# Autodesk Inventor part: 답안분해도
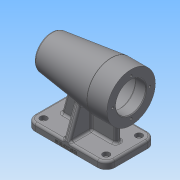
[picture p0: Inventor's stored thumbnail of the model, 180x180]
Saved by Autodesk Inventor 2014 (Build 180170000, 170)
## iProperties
Created: 2018-09
Part Number: 답안분해도
Material: 일반
Document SubType Name: Modeling
Designer: net
Density: 1 g/cm^3
Appearance: 기본값
Author: net
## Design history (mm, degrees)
sketch "스케치1"
  geometry: L1 (56, -34)-(-56, -34); L2 (-56, -34)-(-56, 34); L3 (-56, 34)-(56, 34); L4 (56, 34)-(56, -34); L5 (56, -34)-(-56, 34); L6 (-56, -34)-(56, 34); L7 (-28, 34)-(56, 23.686); L8 (50, 10.5)-(50, 0); L9 (50, 10.5)-(47, 10.5); L10 (47, 10.5)-(47, 0); L11 (47, 10.5)-(47, 16); L12 (47, 16)-(43, 16); L13 (43, 16)-(43, 0); L14 (43, 16)-(43, 17.5); L15 (43, 17.5)-(25, 17.5); L16 (25, 17.5)-(25, 0); L17 (25, 17.5)-(25, 21); L18 (25, 21)-(13, 21); L19 (13, 21)-(13, 0); L20 (13, 21)-(13, 24); L21 (13, 24)-(-41, 24); L22 (-41, 24)-(-41, 0); L23 (-41, 21)-(-56, 21); A1 r 80 centre (-20.413, 0) between (56, -23.686) and (56, 23.686); 4 further points
  constraints: 46 end point, 8 perpendicular, 5 point on line, 5 vertical, 4 collinear, 3 midpoint, 3 point on circle, 2 parallel, 1 centre point, 1 horizontal, 1 horizontal alignment, 10 other
  dimensions: "d0" = 112 distance of L2.end L3.end; "d1" = 28 distance from line of L2 L7.start; "d2" = 7 deg angle of L3 L7; "d3" = 68 dimension on L3; "d4" = 80 radius of A1; "d5" = 15 distance of L23.start L23.end; "d6" = 54 distance of L20.end L21.end; "d7" = 12 distance of L17.end L18.end; "d8" = 18 distance of L14.end L15.end; "d9" = 4 distance of L11.end L12.end; "d10" = 3 distance of L8.start L9.end; "d11" = 21 dimension on L9; "d12" = 32 dimension on L12; "d13" = 35 dimension on L15; "d14" = 42 dimension on L18; "d15" = 48 dimension on L21; "d16" = 42 dimension on L23
revolve "회전1" sketch "스케치1" stored, may be unused: angle "d17" = 90 deg
fillet "모깎기1" dims "d18" = 3
node "작업 평면1"
sketch "스케치2"
  geometry: L1 (-44, -35)-(44, -35); L2 (56, -23)-(56, 23); L3 (44, 35)-(-44, 35); L4 (-56, 23)-(-56, -23); L5 (-56, -35)-(56, 35); L6 (56, -35)-(-56, 35); A1 r 12 centre (-44, 23) between (-44, 35) and (-56, 23); A2 r 12 centre (-44, -23) between (-56, -23) and (-44, -35); A3 r 12 centre (44, -23) between (44, -35) and (56, -23); A4 r 12 centre (44, 23) between (56, 23) and (44, 35); 1 further point
  constraints: 12 end point, 8 point on circle, 8 point on line, 8 tangent, 4 centre point, 3 equal radius, 2 midpoint, 2 parallel, 1 horizontal, 1 perpendicular
  dimensions: "d20" = 112 distance of L5.end L6.end; "d21" = 70 distance of L6.start L5.end; "d22" = 12 radius of A1
extrude "돌출1" join sketch "스케치2" distance "d23" = 10; taper "d24" = 0 deg
sketch "스케치5"
  geometry: L1 (56, -23)-(56, 23) reference; L2 (-38, -4)-(38, -4); L3 (38, -4)-(38, 4); L4 (38, 4)-(-38, 4); L5 (-38, 4)-(-38, -4); L6 (-38, -4)-(38, 4); L7 (38, -4)-(-38, 4); 1 further point
  constraints: 12 end point, 2 midpoint, 2 parallel, 1 horizontal, 1 perpendicular
  dimensions: "d32" = 8 distance of L2.end L3.end; "d33" = 18 distance between parallel lines of L1 L3
extrude "돌출3" join sketch "스케치5" stored distance "d34" = 8; taper "d35" = 0 deg
feature "면 기울기1" dims angle "d36" = 15 deg
fillet "모깎기3" dims "d38" = 3
node "작업 평면2"
sketch "스케치18" dims "d62" = 52
  geometry: L1 (0, 0)-(-26, 0); C1 r 34 at (0, 0) reference; 1 further point
  constraints: 2 coincident, 2 end point, 1 horizontal, 1 horizontal alignment, 2 other
hole "구멍1" sketch "스케치18" at (-26, 0) diameter "d63" = 3.242; stored, may be unused: countersink angle "d67" = 90 deg, drill point angle "d69" = 118 deg; dims "d64" = 8, "d65" = 4, "d66" = 2, "d68" = 11
sketch "스케치20"
  geometry: L1 (35, -64)-(35, -74) reference; L2 (35, -74)-(-35, -74) reference; L3 (-35, -74)-(-35, -64) reference; L4 (-35, -64)-(-4, -64) reference; L5 (-4, -64)-(-4, -30.299) reference; L6 (4, -30.299)-(4, -64) reference; L7 (4, -64)-(35, -64) reference; L8 (-20.089, -23.032)-(-35, -64); C1 r 24 at (0, 0) reference; A1 r 30.562 centre (0, 0) between (4, -30.299) and (-4, -30.299) reference; 1 further point
  constraints: 2 end point, 1 point on circle
  dimensions: "d73" = 20 deg angle of L3 L8
extrude "돌출8" join sketch "스케치20" distance "d74" = 4; taper "d75" = 0 deg
node "작업 평면3"
sketch "스케치21"
  geometry: L1 (4, -64)-(35, -64) reference; L2 (35, -64)-(35, -74) reference; L3 (35, -74)-(-35, -74) reference; L4 (-35, -74)-(-35, -64) reference; L5 (-35, -64)-(-4, -64) reference; L6 (-4, -64)-(-4, -29.804) reference; L7 (4, -29.804)-(4, -64) reference; L8 (-19.909, -22.537)-(-35, -64); C1 r 24 at (0, 0) reference; A1 r 30.071 centre (0, 0) between (4, -29.804) and (-4, -29.804) reference; 1 further point
  constraints: 2 end point, 1 point on circle
  dimensions: "d77" = 20 deg angle of L8 L4
extrude "돌출9" join sketch "스케치21" distance "d78" = 4; taper "d79" = 0 deg
fillet "모깎기7" dims "d80" = 3
fillet "모깎기8" dims "d81" = 3
sketch "스케치22"
  geometry: C1 r 4.75 at (-44, 23); C2 r 2.75 at (-44, 23); C3 r 2.75 at (-44, -23); C4 r 4.75 at (-44, -23); A1 r 9 centre (-44, 23) between (-44, 32) and (-53, 23) reference; A2 r 9 centre (-44, -23) between (-53, -23) and (-44, -32) reference; 1 further point
  constraints: 4 centre point, 4 coincident
  dimensions: "d82" = 9.5 diameter of C1; "d83" = 5.5 diameter of C2; "d88" = 5.5 diameter of C3; "d89" = 9.5 diameter of C4
extrude "돌출10" cut sketch "스케치22" distance "d84" = 5.4; taper "d85" = 0 deg
extrude "돌출11" cut sketch "스케치22" stored distance "d86" = 5.4; taper "d87" = 0 deg
sketch "스케치23"
  geometry: C1 r 2.75 at (44, 23); C2 r 4.75 at (44, 23); C3 r 2.75 at (44, -23); C4 r 4.75 at (44, -23); A1 r 9 centre (44, -23) between (44, -32) and (53, -23) reference; A2 r 9 centre (44, 23) between (53, 23) and (44, 32) reference; 1 further point
  constraints: 4 centre point, 4 coincident
  dimensions: "d90" = 5.5 diameter of C1; "d91" = 9.5 diameter of C2; "d92" = 5.5 diameter of C3; "d93" = 9.5 diameter of C4
extrude "돌출12" cut sketch "스케치23" distance "d94" = 5.4; taper "d95" = 0 deg
extrude "돌출13" cut sketch "스케치23" stored distance "d96" = 5.4; taper "d97" = 0 deg
fillet "모깎기9" dims "d98" = 3, "d99" = 0.3
chamfer "모따기1" distance "d100" = 1; stored, may be unused: second distance "d101" = 2, angle "d102" = 45 deg
sketch "스케치24"
  geometry: L1 (88, 0)-(100, 0) reference; L2 (100, 0)-(100, 7) reference; 2 further points
  constraints: 1 other
  dimensions: "d103" = 3 distance from line of L1 point (44, 3); "d104" = 56 distance from line of L2 point (44, 3)
feature "엠보싱1" sketch "스케치24" dims "d0" = 112, "d1" = 28, "d2" = 7 deg, "d3" = 68, "d4" = 80, "d5" = 15, "d6" = 54, "d7" = 12, "d8" = 18, "d9" = 4, "d10" = 3, "d11" = 21, "d12" = 32, "d13" = 35, "d14" = 42, "d15" = 48, "d16" = 42, "d105" = 0.5, "d106" = 0
node "솔리드1"
pattern_circular "원형 패턴1" dims angle "d71" = 360 deg
mirror "대칭3"
node "절단 모서리 투영8"
node "절단 모서리 투영9"
other parameters: "d19" = -74, "d56" = -4, "d76" = -4
